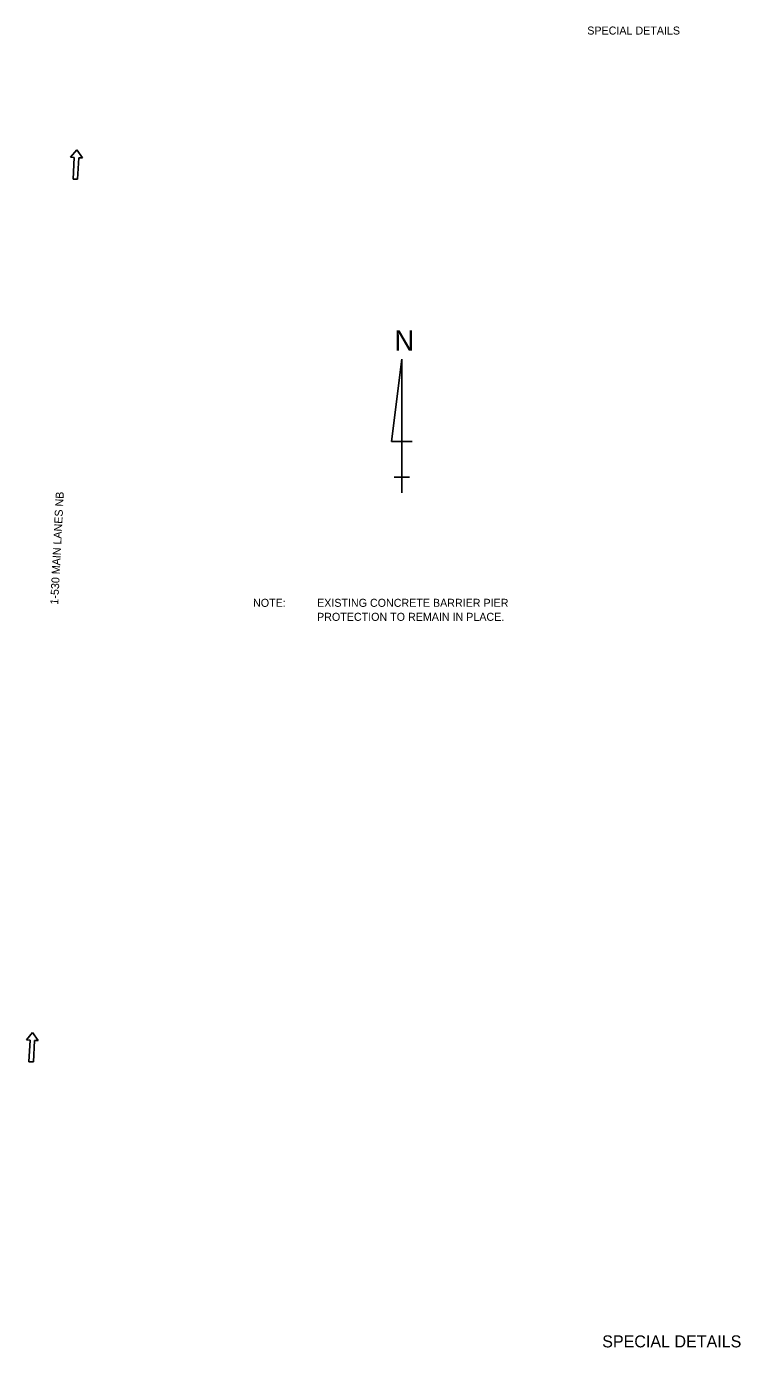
# Model space of a CAD drawing. Extents: x 1230537 to 1231758, y 2055794 to 2056784.
# Drawn here: x 1231223 to 1231758, y 2055794 to 2056784 of the extents above; entities that cross this region are included whole.
import ezdxf

# ---------------------------------------------------------------- set-up
doc = ezdxf.new("R2010")
doc.units = 0
for name, color, linetype in [('1', 7, 'Continuous'), ('2', 7, 'Continuous'), ('63', 7, 'Continuous'), ('Default', 7, 'Continuous'), ('G-ANNO-TEXT', 7, 'Continuous')]:
    doc.layers.add(name, color=color, linetype=linetype)

msp = doc.modelspace()

# ---------------------------------------------------------------- linework, layer by layer
at = {"layer": '63'}
for p, q in [((1231504.33, 2056534.4), (1231496.64, 2056472.87)), ((1231504.33, 2056434.4), (1231504.33, 2056534.4)), ((1231504.33, 2056534.4), (1231504.33, 2056457.48)), ((1231496.64, 2056472.87), (1231512.02, 2056472.87)), ((1231504.33, 2056434.4), (1231504.33, 2056457.48)), ((1231504.33, 2056445.94), (1231498.56, 2056445.94)), ((1231498.56, 2056445.94), (1231510.1, 2056445.94)), ((1231504.33, 2056434.4), (1231504.33, 2056445.94))]:
    msp.add_line(p, q, dxfattribs=at)
at = {"layer": 'Default'}
for p, q in [((1231255.88, 2056685.79), (1231260.57, 2056691.28)), ((1231260.57, 2056691.28), (1231264.69, 2056685.34)), ((1231255.88, 2056685.79), (1231258.63, 2056685.65)), ((1231258.63, 2056685.65), (1231257.82, 2056669.46)), ((1231261.94, 2056685.48), (1231261.12, 2056669.29)), ((1231261.94, 2056685.48), (1231264.69, 2056685.34)), ((1231257.82, 2056669.46), (1231261.12, 2056669.29)), ((1231222.69, 2056024.19), (1231227.38, 2056029.68)), ((1231222.69, 2056024.19), (1231225.44, 2056024.05)), ((1231225.44, 2056024.05), (1231224.63, 2056007.86)), ((1231227.38, 2056029.68), (1231231.49, 2056023.75)), ((1231228.74, 2056023.89), (1231227.93, 2056007.7)), ((1231228.74, 2056023.89), (1231231.49, 2056023.75)), ((1231224.63, 2056007.86), (1231227.93, 2056007.7))]:
    msp.add_line(p, q, dxfattribs=at)

# ---------------------------------------------------------------- texts
at = {"layer": '1'}
for s, p in [('NOTE:', (1231392.72, 2056348.84)), ('EXISTING CONCRETE BARRIER PIER', (1231440.72, 2056348.84)), ('PROTECTION TO REMAIN IN PLACE.', (1231440.72, 2056338.34))]:
    msp.add_text(s, height=6, dxfattribs=at).set_placement(p)
at = {"layer": '2'}
msp.add_text('1-530 MAIN LANES NB', height=6, rotation=87.13211, dxfattribs=at).set_placement((1231246.53, 2056350.41))
at = {"layer": '63'}
msp.add_text('N', height=15.38, dxfattribs=at).set_placement((1231498.7, 2056540.81))
at = {"layer": 'G-ANNO-TEXT'}
for height, p in [(6, (1231643.39, 2056777.8)), (9, (1231654.61, 2055793.73))]:
    msp.add_text('SPECIAL DETAILS', height=height, dxfattribs=at).set_placement(p)

doc.saveas('drawing.dxf')
